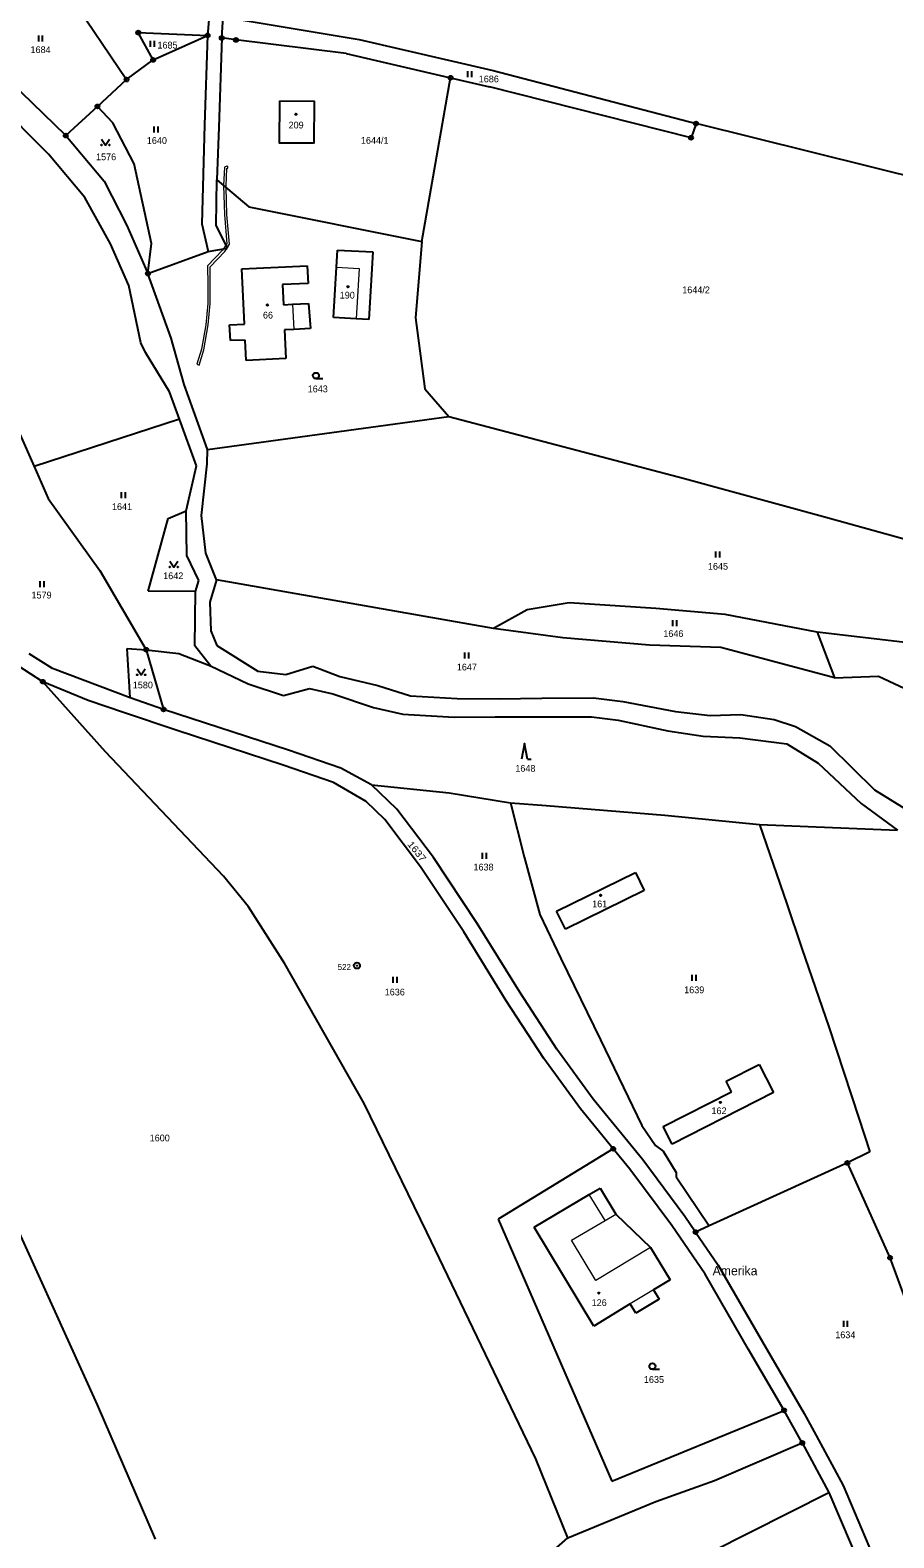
# Model space of a CAD drawing. Extents: x -601131 to -597152, y -1058536 to -1055911.
# Drawn here: x -599395.7 to -599178.6, y -1057934.2 to -1057555.3 of the extents above; entities that cross this region are included whole.
import ezdxf
from ezdxf.enums import TextEntityAlignment as Align

# ---------------------------------------------------------------- set-up
doc = ezdxf.new("R2010")
doc.units = 0
doc.header["$LTSCALE"] = 0.68
for name, color, linetype, lineweight in [('1', 7, 'Continuous', 25), ('13', 7, 'Continuous', 13), ('3', 7, 'Continuous', 25), ('4', 7, 'Continuous', 13), ('5', 7, 'Continuous', 25), ('7', 7, 'Continuous', 13), ('8', 7, 'Continuous', 25)]:
    doc.layers.add(name, color=color, linetype=linetype, lineweight=lineweight)
doc.layers.add('2', color=7, linetype='Continuous')

msp = doc.modelspace()

# ---------------------------------------------------------------- linework, layer by layer
at = {"layer": '1'}
for p, q in [((-599347.34, -1057512.42), (-599351.06, -1057556.67)), ((-599390.32, -1057539.74), (-599371.44, -1057567.75)), ((-599347.53, -1057557.31), (-599347.19, -1057551.97)), ((-599347.19, -1057551.97), (-599313.01, -1057557.68)), ((-599364.77, -1057562.83), (-599368.49, -1057555.97)), ((-599368.49, -1057555.97), (-599351.06, -1057556.67)), ((-599364.77, -1057562.83), (-599351.06, -1057556.67)), ((-599351.06, -1057556.67), (-599351.89, -1057579.12)), ((-599347.53, -1057557.31), (-599348.25, -1057579.76)), ((-599343.95, -1057557.81), (-599347.53, -1057557.31)), ((-599316.25, -1057561.2), (-599343.95, -1057557.81)), ((-599313.01, -1057557.68), (-599279.26, -1057565.52)), ((-599371.44, -1057567.75), (-599364.77, -1057562.83)), ((-599316.25, -1057561.2), (-599289.98, -1057567.31)), ((-599386.72, -1057581.85), (-599403.43, -1057565.64)), ((-599289.98, -1057567.31), (-599280.18, -1057569.59)), ((-599279.26, -1057565.52), (-599228.31, -1057578.81)), ((-599391.04, -1057586.5), (-599407.5, -1057570.06)), ((-599378.75, -1057574.49), (-599371.44, -1057567.75)), ((-599229.56, -1057582.38), (-599280.18, -1057569.59)), ((-599378.75, -1057574.49), (-599386.72, -1057581.85)), ((-599374.93, -1057578.65), (-599378.75, -1057574.49)), ((-599369.53, -1057588.91), (-599374.93, -1057578.65)), ((-599386.72, -1057581.85), (-599377.06, -1057593.32)), ((-599351.89, -1057579.12), (-599352.55, -1057604.04)), ((-599348.25, -1057579.76), (-599348.76, -1057592.94)), ((-599228.31, -1057578.81), (-599229.56, -1057582.38)), ((-599081.27, -1057615.35), (-599228.31, -1057578.81)), ((-599381.95, -1057597.37), (-599391.04, -1057586.5)), ((-599365.18, -1057608.99), (-599369.53, -1057588.91)), ((-599377.06, -1057593.32), (-599371.37, -1057604.42)), ((-599348.92, -1057604.31), (-599348.76, -1057592.94)), ((-599348.76, -1057592.94), (-599340.71, -1057599.72)), ((-599375.47, -1057609.07), (-599381.95, -1057597.37)), ((-599371.37, -1057604.42), (-599366.06, -1057616.5)), ((-599352.55, -1057604.04), (-599350.91, -1057610.98)), ((-599346.11, -1057610.16), (-599348.92, -1057604.31)), ((-599370.85, -1057619.51), (-599375.47, -1057609.07)), ((-599366.06, -1057616.5), (-599365.18, -1057608.99)), ((-599297.25, -1057608.48), (-599298.78, -1057627.63)), ((-599366.06, -1057616.5), (-599350.91, -1057610.98)), ((-599350.91, -1057610.98), (-599346.11, -1057610.16)), ((-599318.7, -1057614.89), (-599318.45, -1057610.59)), ((-599318.45, -1057610.59), (-599309.51, -1057611.02)), ((-599309.51, -1057611.02), (-599310.54, -1057628.03)), ((-599360.26, -1057632.7), (-599366.06, -1057616.5)), ((-599342.5, -1057615.32), (-599326.01, -1057614.58)), ((-599341.84, -1057629.24), (-599342.5, -1057615.32)), ((-599326.01, -1057614.58), (-599325.8, -1057618.97)), ((-599319.43, -1057627.53), (-599318.7, -1057614.89)), ((-599367.85, -1057633.87), (-599370.85, -1057619.51)), ((-599325.8, -1057618.97), (-599332.25, -1057619.28)), ((-599332.25, -1057619.28), (-599332, -1057624.33)), ((-599332, -1057624.33), (-599329.73, -1057624.22)), ((-599329.73, -1057624.22), (-599325.71, -1057624.06)), ((-599325.71, -1057624.06), (-599325.23, -1057630.35)), ((-599313.69, -1057627.85), (-599319.43, -1057627.53)), ((-599310.54, -1057628.03), (-599313.69, -1057627.85)), ((-599298.78, -1057627.63), (-599296.49, -1057645.44)), ((-599345.54, -1057629.43), (-599341.84, -1057629.24)), ((-599345.34, -1057633.33), (-599345.54, -1057629.43)), ((-599329.43, -1057630.52), (-599331.73, -1057630.63)), ((-599331.73, -1057630.63), (-599331.38, -1057637.87)), ((-599325.23, -1057630.35), (-599329.43, -1057630.52)), ((-599366.65, -1057636.35), (-599367.85, -1057633.87)), ((-599356.95, -1057644.41), (-599360.26, -1057632.7)), ((-599341.67, -1057633.25), (-599345.34, -1057633.33)), ((-599341.39, -1057638.37), (-599341.67, -1057633.25)), ((-599360.64, -1057646.2), (-599366.65, -1057636.35)), ((-599331.38, -1057637.87), (-599341.39, -1057638.37)), ((-599358.14, -1057653.05), (-599360.64, -1057646.2)), ((-599351.12, -1057660.75), (-599356.95, -1057644.41)), ((-599296.49, -1057645.44), (-599290.42, -1057652.42)), ((-599353.84, -1057664.85), (-599358.14, -1057653.05)), ((-599351.12, -1057660.75), (-599290.42, -1057652.42)), ((-599290.42, -1057652.42), (-599231.18, -1057667.97)), ((-599398.23, -1057656.83), (-599394.65, -1057664.97)), ((-599351.18, -1057664.33), (-599351.12, -1057660.75)), ((-599356.43, -1057676.09), (-599353.84, -1057664.85)), ((-599352.63, -1057677.32), (-599351.18, -1057664.33)), ((-599231.18, -1057667.97), (-599196.28, -1057677.56)), ((-599391.11, -1057673), (-599378.18, -1057691.08)), ((-599361.02, -1057678.01), (-599356.43, -1057676.09)), ((-599356.33, -1057687.37), (-599356.43, -1057676.09)), ((-599366, -1057696.32), (-599361.02, -1057678.01)), ((-599351.51, -1057686.73), (-599352.63, -1057677.32)), ((-599196.28, -1057677.56), (-599135.55, -1057694.34)), ((-599353.27, -1057693.67), (-599356.33, -1057687.37)), ((-599348.8, -1057693.49), (-599351.51, -1057686.73)), ((-599378.18, -1057691.08), (-599366.5, -1057711.02)), ((-599354.09, -1057696.36), (-599353.27, -1057693.67)), ((-599348.8, -1057693.49), (-599350.52, -1057699.04)), ((-599279.18, -1057705.69), (-599348.8, -1057693.49)), ((-599354.09, -1057696.36), (-599366, -1057696.32)), ((-599354.27, -1057710.07), (-599354.09, -1057696.36)), ((-599350.52, -1057699.04), (-599350.26, -1057706.31)), ((-599260.23, -1057699.2), (-599270.75, -1057701.03)), ((-599238.41, -1057700.7), (-599260.23, -1057699.2)), ((-599270.75, -1057701.03), (-599279.18, -1057705.69)), ((-599220.97, -1057702.2), (-599238.41, -1057700.7)), ((-599197.89, -1057706.63), (-599220.97, -1057702.2)), ((-599350.26, -1057706.31), (-599348.75, -1057709.97)), ((-599261.8, -1057708.05), (-599279.18, -1057705.69)), ((-599197.89, -1057706.63), (-599193.52, -1057718.08)), ((-599174.99, -1057709.26), (-599197.89, -1057706.63)), ((-599370.54, -1057723.09), (-599371.28, -1057710.73)), ((-599371.28, -1057710.73), (-599366.5, -1057711.02)), ((-599366.5, -1057711.02), (-599358.31, -1057711.95)), ((-599366.5, -1057711.02), (-599362.13, -1057726.02)), ((-599350.37, -1057715.05), (-599354.27, -1057710.07)), ((-599348.75, -1057709.97), (-599338.42, -1057716.45)), ((-599239.96, -1057709.84), (-599261.8, -1057708.05)), ((-599222.09, -1057710.47), (-599239.96, -1057709.84)), ((-599193.52, -1057718.08), (-599222.09, -1057710.47)), ((-599392.49, -1057719.05), (-599398.67, -1057715.05)), ((-599390.03, -1057715.77), (-599395.94, -1057712.06)), ((-599358.31, -1057711.95), (-599350.37, -1057715.05)), ((-599350.37, -1057715.05), (-599340.91, -1057719.6)), ((-599331.38, -1057717.26), (-599324.65, -1057715.12)), ((-599324.65, -1057715.12), (-599317.81, -1057717.73)), ((-599370.54, -1057723.09), (-599390.03, -1057715.77)), ((-599338.42, -1057716.45), (-599331.38, -1057717.26)), ((-599317.81, -1057717.73), (-599308.32, -1057720.04)), ((-599193.52, -1057718.08), (-599182.44, -1057717.64)), ((-599182.44, -1057717.64), (-599172.09, -1057722.51)), ((-599381.13, -1057723.76), (-599392.49, -1057719.05)), ((-599376.7, -1057736.69), (-599392.49, -1057719.05)), ((-599340.91, -1057719.6), (-599332, -1057722.52)), ((-599332, -1057722.52), (-599325.45, -1057720.73)), ((-599325.45, -1057720.73), (-599319.58, -1057722.08)), ((-599319.58, -1057722.08), (-599309.4, -1057725.53)), ((-599308.32, -1057720.04), (-599300.07, -1057722.61)), ((-599300.07, -1057722.61), (-599288.36, -1057723.26)), ((-599371.97, -1057726.92), (-599381.13, -1057723.76)), ((-599362.13, -1057726.02), (-599370.54, -1057723.09)), ((-599330.72, -1057736.26), (-599362.13, -1057726.02)), ((-599309.4, -1057725.53), (-599302.03, -1057727.23)), ((-599288.36, -1057723.26), (-599277.79, -1057723.4)), ((-599277.79, -1057723.4), (-599267.07, -1057723.2)), ((-599267.07, -1057723.2), (-599254.07, -1057723.13)), ((-599254.07, -1057723.13), (-599246.72, -1057724.06)), ((-599246.72, -1057724.06), (-599233.43, -1057726.51)), ((-599233.43, -1057726.51), (-599224.74, -1057727.54)), ((-599358.72, -1057731.34), (-599371.97, -1057726.92)), ((-599302.03, -1057727.23), (-599289.07, -1057728)), ((-599289.07, -1057728), (-599278.78, -1057727.91)), ((-599278.78, -1057727.91), (-599254.56, -1057727.9)), ((-599254.56, -1057727.9), (-599247.89, -1057728.71)), ((-599247.89, -1057728.71), (-599235.42, -1057731.4)), ((-599224.74, -1057727.54), (-599217.07, -1057727.33)), ((-599217.07, -1057727.33), (-599208.63, -1057728.53)), ((-599208.63, -1057728.53), (-599203.28, -1057730.3)), ((-599203.28, -1057730.3), (-599194.71, -1057735.14)), ((-599332.04, -1057740.04), (-599358.72, -1057731.34)), ((-599235.42, -1057731.4), (-599226.47, -1057732.72)), ((-599226.47, -1057732.72), (-599217.32, -1057733.18)), ((-599217.32, -1057733.18), (-599205.51, -1057734.64)), ((-599347.1, -1057767.95), (-599376.7, -1057736.69)), ((-599317.61, -1057740.78), (-599330.72, -1057736.26)), ((-599205.51, -1057734.64), (-599197.59, -1057739.52)), ((-599194.71, -1057735.14), (-599183.47, -1057746.22)), ((-599319.4, -1057744.35), (-599332.04, -1057740.04)), ((-599309.9, -1057744.98), (-599317.61, -1057740.78)), ((-599197.59, -1057739.52), (-599186.79, -1057749.67)), ((-599311.24, -1057749.12), (-599319.4, -1057744.35)), ((-599303.53, -1057751.07), (-599309.9, -1057744.98)), ((-599309.9, -1057744.98), (-599290.38, -1057747.01)), ((-599306.54, -1057753.7), (-599311.24, -1057749.12)), ((-599290.38, -1057747.01), (-599274.95, -1057749.53)), ((-599183.47, -1057746.22), (-599175.59, -1057751.09)), ((-599294.31, -1057763.24), (-599303.53, -1057751.07)), ((-599274.95, -1057749.53), (-599265.95, -1057750.15)), ((-599274.95, -1057749.53), (-599271.51, -1057763.06)), ((-599265.95, -1057750.15), (-599236.12, -1057752.61)), ((-599236.12, -1057752.61), (-599212.38, -1057754.98)), ((-599186.79, -1057749.67), (-599177.63, -1057756.39)), ((-599297.54, -1057765.59), (-599306.54, -1057753.7)), ((-599212.38, -1057754.98), (-599177.63, -1057756.39)), ((-599212.38, -1057754.98), (-599205.45, -1057774.88)), ((-599283.31, -1057779.78), (-599294.31, -1057763.24)), ((-599271.51, -1057763.06), (-599267.56, -1057777.52)), ((-599340.78, -1057775.6), (-599347.1, -1057767.95)), ((-599286.68, -1057781.94), (-599297.54, -1057765.59)), ((-599263.37, -1057776.73), (-599243.56, -1057767.03)), ((-599243.56, -1057767.03), (-599241.33, -1057771.51)), ((-599241.33, -1057771.51), (-599261.13, -1057781.23)), ((-599331.69, -1057789.95), (-599340.78, -1057775.6)), ((-599205.45, -1057774.88), (-599201.73, -1057786.06)), ((-599267.56, -1057777.52), (-599262.25, -1057788.63)), ((-599261.13, -1057781.23), (-599263.37, -1057776.73)), ((-599275.99, -1057799.24), (-599286.68, -1057781.94)), ((-599272.62, -1057797.09), (-599283.31, -1057779.78)), ((-599201.73, -1057786.06), (-599194.91, -1057805.8)), ((-599311.71, -1057825.01), (-599331.69, -1057789.95)), ((-599262.25, -1057788.63), (-599252.32, -1057809.04)), ((-599263.28, -1057811.41), (-599272.62, -1057797.09)), ((-599266.56, -1057813.7), (-599275.99, -1057799.24)), ((-599194.91, -1057805.8), (-599187.38, -1057828.71)), ((-599252.32, -1057809.04), (-599241.91, -1057830.58)), ((-599254.13, -1057823.99), (-599263.28, -1057811.41)), ((-599257.31, -1057826.41), (-599266.56, -1057813.7)), ((-599220.72, -1057819.45), (-599212.43, -1057815.26)), ((-599212.43, -1057815.26), (-599208.82, -1057822.32)), ((-599219.42, -1057822.07), (-599220.72, -1057819.45)), ((-599295.95, -1057857.38), (-599311.71, -1057825.01)), ((-599241.69, -1057839.23), (-599254.13, -1057823.99)), ((-599236.56, -1057830.83), (-599219.42, -1057822.07)), ((-599208.82, -1057822.32), (-599234.28, -1057835.24)), ((-599249.13, -1057836.43), (-599257.31, -1057826.41)), ((-599187.38, -1057828.71), (-599184.63, -1057837.22)), ((-599241.91, -1057830.58), (-599238.5, -1057835.57)), ((-599234.28, -1057835.24), (-599236.56, -1057830.83)), ((-599238.5, -1057835.57), (-599236.57, -1057837.01)), ((-599406.99, -1057838.84), (-599378.8, -1057900.74)), ((-599249.13, -1057836.43), (-599278, -1057854.12)), ((-599244.98, -1057841.51), (-599249.13, -1057836.43)), ((-599231.15, -1057853.4), (-599241.69, -1057839.23)), ((-599236.57, -1057837.01), (-599233.27, -1057842.4)), ((-599190.27, -1057839.98), (-599225.04, -1057855.82)), ((-599184.63, -1057837.22), (-599190.27, -1057839.98)), ((-599179.53, -1057863.81), (-599190.27, -1057839.98)), ((-599234.41, -1057855.72), (-599244.98, -1057841.51)), ((-599233.27, -1057842.4), (-599233.27, -1057843.5)), ((-599233.27, -1057843.5), (-599225.04, -1057855.82)), ((-599255.13, -1057847.87), (-599252.39, -1057846.31)), ((-599252.39, -1057846.31), (-599248.45, -1057852.82)), ((-599269.03, -1057856.13), (-599255.13, -1057847.87)), ((-599278, -1057854.12), (-599249.44, -1057919.96)), ((-599248.45, -1057852.82), (-599239.71, -1057861.2)), ((-599228.42, -1057857.36), (-599231.15, -1057853.4)), ((-599268.57, -1057914.33), (-599295.95, -1057857.38)), ((-599254, -1057880.98), (-599269.03, -1057856.13)), ((-599226.01, -1057867.91), (-599234.41, -1057855.72)), ((-599225.04, -1057855.82), (-599228.42, -1057857.36)), ((-599228.42, -1057857.36), (-599222.71, -1057865.66)), ((-599239.71, -1057861.2), (-599234.81, -1057869.34)), ((-599222.71, -1057865.66), (-599211.59, -1057884.93)), ((-599175.5, -1057874.75), (-599179.53, -1057863.81)), ((-599234.81, -1057869.34), (-599239, -1057871.88)), ((-599215.09, -1057886.87), (-599226.01, -1057867.91)), ((-599237.61, -1057874.17), (-599243.45, -1057877.71)), ((-599239, -1057871.88), (-599237.61, -1057874.17)), ((-599244.84, -1057875.42), (-599254, -1057880.98)), ((-599243.45, -1057877.71), (-599244.84, -1057875.42)), ((-599211.59, -1057884.93), (-599201.09, -1057902.95)), ((-599206.19, -1057902.15), (-599215.09, -1057886.87)), ((-599378.8, -1057900.74), (-599364.29, -1057934.51)), ((-599249.44, -1057919.96), (-599206.19, -1057902.15)), ((-599201.6, -1057910.34), (-599206.19, -1057902.15)), ((-599201.09, -1057902.95), (-599198.07, -1057908.46)), ((-599223.63, -1057919.8), (-599201.6, -1057910.34)), ((-599201.6, -1057910.34), (-599194.94, -1057922.77)), ((-599198.07, -1057908.46), (-599191.33, -1057921.05)), ((-599260.49, -1057934.17), (-599268.57, -1057914.33)), ((-599238.41, -1057925.08), (-599223.63, -1057919.8)), ((-599234.5, -1057942.72), (-599194.94, -1057922.77)), ((-599194.94, -1057922.77), (-599183.25, -1057949.98)), ((-599191.33, -1057921.05), (-599179.75, -1057948.32)), ((-599260.49, -1057934.17), (-599238.41, -1057925.08)), ((-599293.04, -1057962.61), (-599260.49, -1057934.17))]:
    msp.add_line(p, q, dxfattribs=at)
for points in [[(-599340.71, -1057599.72), (-599297.25, -1057608.48), (-599289.98, -1057567.31)], [(-599358.14, -1057653.05), (-599394.65, -1057664.97), (-599391.11, -1057673)]]:
    msp.add_lwpolyline(points, dxfattribs=at)
msp.add_lwpolyline([(-599332.9, -1057573.11), (-599324.3, -1057573.16), (-599324.38, -1057583.76), (-599332.98, -1057583.71)], close=True, dxfattribs=at)
at = {"layer": '13'}
for points in [[(-599347.04, -1057594.39), (-599346.42, -1057594.91), (-599346.44, -1057594.43), (-599346.27, -1057590.12), (-599346, -1057590.02), (-599345.96, -1057589.58), (-599346.22, -1057589.56), (-599346.85, -1057589.78)], [(-599346.42, -1057594.91), (-599347.04, -1057594.39), (-599346.81, -1057601.67), (-599346.23, -1057609), (-599346.48, -1057609.39), (-599346.17, -1057610.03), (-599345.61, -1057609.16), (-599346.21, -1057601.63)], [(-599346.28, -1057610.19), (-599347.08, -1057610.33), (-599347.3, -1057610.64), (-599351.06, -1057614.54), (-599351, -1057619.35), (-599351.01, -1057624.04), (-599351.51, -1057629.35), (-599352.59, -1057635.51), (-599353.77, -1057639.31), (-599353.19, -1057639.49), (-599352.01, -1057635.65), (-599350.91, -1057629.43), (-599350.41, -1057624.06), (-599350.4, -1057619.35), (-599350.46, -1057614.78), (-599346.78, -1057610.97)], [(-599347.08, -1057610.33), (-599346.28, -1057610.19), (-599346.17, -1057610.03), (-599346.48, -1057609.39)]]:
    msp.add_lwpolyline(points, close=True, dxfattribs=at)
at = {"layer": '3'}
for p, q in [((-599393.531, -1057558.17), (-599393.531, -1057556.67)), ((-599392.53, -1057558.17), (-599392.53, -1057556.67)), ((-599365.431, -1057559.57), (-599365.431, -1057558.07)), ((-599364.43, -1057559.57), (-599364.43, -1057558.07)), ((-599285.691, -1057567.18), (-599285.691, -1057565.68)), ((-599284.69, -1057567.18), (-599284.69, -1057565.68)), ((-599364.491, -1057581.04), (-599364.491, -1057579.54)), ((-599363.49, -1057581.04), (-599363.49, -1057579.54)), ((-599323.843, -1057642.91), (-599322.093, -1057642.91)), ((-599372.731, -1057672.93), (-599372.731, -1057671.43)), ((-599371.73, -1057672.93), (-599371.73, -1057671.43)), ((-599223.331, -1057687.88), (-599223.331, -1057686.38)), ((-599222.33, -1057687.88), (-599222.33, -1057686.38)), ((-599393.191, -1057695.31), (-599393.191, -1057693.81)), ((-599392.19, -1057695.31), (-599392.19, -1057693.81)), ((-599234.161, -1057705.13), (-599234.161, -1057703.63)), ((-599233.16, -1057705.13), (-599233.16, -1057703.63)), ((-599286.421, -1057713.19), (-599286.421, -1057711.69)), ((-599285.42, -1057713.19), (-599285.42, -1057711.69)), ((-599270.7, -1057738.55), (-599269.704, -1057738.55)), ((-599281.971, -1057763.55), (-599281.971, -1057762.05)), ((-599280.97, -1057763.55), (-599280.97, -1057762.05)), ((-599304.431, -1057794.73), (-599304.431, -1057793.23)), ((-599303.43, -1057794.73), (-599303.43, -1057793.23)), ((-599229.291, -1057794.25), (-599229.291, -1057792.75)), ((-599228.29, -1057794.25), (-599228.29, -1057792.75)), ((-599191.191, -1057881.18), (-599191.191, -1057879.68)), ((-599190.19, -1057881.18), (-599190.19, -1057879.68)), ((-599239.273, -1057891.82), (-599237.523, -1057891.82))]:
    msp.add_line(p, q, dxfattribs=at)
for points in [[(-599377.77, -1057582.709), (-599376.77, -1057584.21), (-599375.77, -1057582.709)], [(-599360.56, -1057688.749), (-599359.56, -1057690.25), (-599358.56, -1057688.749)], [(-599368.77, -1057715.809), (-599367.77, -1057717.31), (-599366.77, -1057715.809)], [(-599270.7, -1057738.55), (-599271.45, -1057734.55), (-599272.2, -1057738.55)]]:
    msp.add_lwpolyline(points, dxfattribs=at)
for centre, radius in [((-599377.77, -1057584.2095), 0.1), ((-599375.77, -1057584.2095), 0.1), ((-599323.8429, -1057642.1598), 0.75), ((-599360.56, -1057690.2495), 0.1), ((-599358.56, -1057690.2495), 0.1), ((-599368.77, -1057717.3095), 0.1), ((-599366.77, -1057717.3095), 0.1), ((-599239.2729, -1057891.0698), 0.75)]:
    msp.add_circle(centre, radius, dxfattribs=at)
at = {"layer": '4'}
for p, q in [((-599318.7, -1057614.89), (-599312.96, -1057615.27)), ((-599312.96, -1057615.27), (-599313.69, -1057627.85)), ((-599329.73, -1057624.22), (-599329.43, -1057630.52)), ((-599251.16, -1057854.4), (-599255.13, -1057847.87)), ((-599259.62, -1057859.39), (-599251.16, -1057854.4)), ((-599251.16, -1057854.4), (-599248.45, -1057852.82)), ((-599253.52, -1057869.53), (-599259.62, -1057859.39)), ((-599239.71, -1057861.2), (-599253.52, -1057869.53)), ((-599239, -1057871.88), (-599244.84, -1057875.42))]:
    msp.add_line(p, q, dxfattribs=at)
at = {"layer": '5'}
for centre in [(-599328.8668, -1057576.4792), (-599315.8168, -1057619.8292), (-599336.0268, -1057624.3992), (-599252.2868, -1057772.7392), (-599222.1668, -1057824.7592), (-599252.7368, -1057872.6792)]:
    msp.add_circle(centre, 0.175, dxfattribs=at)
at = {"layer": '8'}
for centre, radius in [((-599368.49, -1057555.9699), 0.5), ((-599368.49, -1057555.9699), 0.0303), ((-599351.06, -1057556.6699), 0.5), ((-599351.06, -1057556.6699), 0.0303), ((-599347.53, -1057557.3099), 0.5), ((-599347.53, -1057557.3099), 0.0303), ((-599343.95, -1057557.8099), 0.5), ((-599343.95, -1057557.8099), 0.0303), ((-599364.77, -1057562.8299), 0.5), ((-599364.77, -1057562.8299), 0.0303), ((-599371.44, -1057567.7499), 0.5), ((-599289.98, -1057567.3099), 0.5), ((-599289.98, -1057567.3099), 0.0303), ((-599371.44, -1057567.7499), 0.0303), ((-599378.75, -1057574.4899), 0.5), ((-599378.75, -1057574.4899), 0.0303), ((-599228.31, -1057578.8099), 0.5), ((-599228.31, -1057578.8099), 0.0303), ((-599386.72, -1057581.8499), 0.5), ((-599386.72, -1057581.8499), 0.0303), ((-599229.56, -1057582.3799), 0.5), ((-599229.56, -1057582.3799), 0.0303), ((-599366.06, -1057616.4999), 0.5), ((-599366.06, -1057616.4999), 0.0303), ((-599366.5, -1057711.0199), 0.5), ((-599366.5, -1057711.0199), 0.0303), ((-599392.49, -1057719.0499), 0.5), ((-599392.49, -1057719.0499), 0.0303), ((-599362.13, -1057726.0199), 0.5), ((-599362.13, -1057726.0199), 0.0303), ((-599313.54, -1057790.3898), 0.75), ((-599313.54, -1057790.3898), 0.03), ((-599249.13, -1057836.4299), 0.5), ((-599249.13, -1057836.4299), 0.0303), ((-599190.27, -1057839.9799), 0.5), ((-599190.27, -1057839.9799), 0.0303), ((-599228.42, -1057857.3599), 0.5), ((-599228.42, -1057857.3599), 0.0303), ((-599179.53, -1057863.8099), 0.5), ((-599179.53, -1057863.8099), 0.0303), ((-599206.19, -1057902.1499), 0.5), ((-599206.19, -1057902.1499), 0.0303), ((-599201.6, -1057910.3399), 0.5), ((-599201.6, -1057910.3399), 0.0303)]:
    msp.add_circle(centre, radius, dxfattribs=at)

# ---------------------------------------------------------------- texts
at = {"layer": '2'}
for s, p in [('1684', (-599393.06, -1057561.102)), ('1685', (-599361.15, -1057559.962)), ('1686', (-599280.39, -1057568.462)), ('1640', (-599363.82, -1057583.932)), ('1576', (-599376.58, -1057588.022)), ('190', (-599315.969, -1057622.782)), ('66', (-599335.899, -1057627.802)), ('1643', (-599323.39, -1057646.332)), ('1641', (-599372.59, -1057675.922)), ('1642', (-599359.7, -1057693.292)), ('1645', (-599222.79, -1057690.922)), ('1579', (-599392.81, -1057698.152)), ('1646', (-599234, -1057707.832)), ('1647', (-599285.9, -1057716.222)), ('1580', (-599367.35, -1057720.742)), ('1648', (-599271.2, -1057741.682)), ('1638', (-599281.72, -1057766.492)), ('161', (-599252.519, -1057775.742)), ('1636', (-599304.03, -1057797.892)), ('1639', (-599228.76, -1057797.332)), ('162', (-599222.529, -1057827.722)), ('1600', (-599363.11, -1057834.552)), ('126', (-599252.649, -1057875.932)), ('1634', (-599190.78, -1057884.022)), ('1635', (-599238.88, -1057895.242))]:
    msp.add_text(s, height=1.7, dxfattribs=at).set_placement(p, align=Align.CENTER)
for s, p in [('209', (-599330.72, -1057580.045)), ('1644/1', (-599312.54, -1057583.895)), ('1644/2', (-599231.77, -1057621.455))]:
    msp.add_text(s, height=1.7, dxfattribs=at).set_placement(p)
at = {"layer": '2', "width": 1.15}
msp.add_text('1637', height=1.7, rotation=309, dxfattribs=at).set_placement((-599299.1255, -1057762.2191), align=Align.CENTER)
at = {"layer": '7'}
msp.add_text('Amerika', height=2.3, dxfattribs=at).set_placement((-599218.5, -1057868.214), align=Align.CENTER)
at = {"layer": '8'}
msp.add_text('522', height=1.5, dxfattribs=at).set_placement((-599315.039, -1057791.507), align=Align.RIGHT)

doc.saveas('drawing.dxf')
